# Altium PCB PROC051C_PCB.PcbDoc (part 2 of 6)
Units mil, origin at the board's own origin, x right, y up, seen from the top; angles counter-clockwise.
Board outline 3304.03 x 2647.77 mil, 6 copper layers (TOP, L2, L3, L4, L5, BOTTOM), stack 55.54 mil thick; 370 components, 273 nets, 1273 pads, 1381 vias.
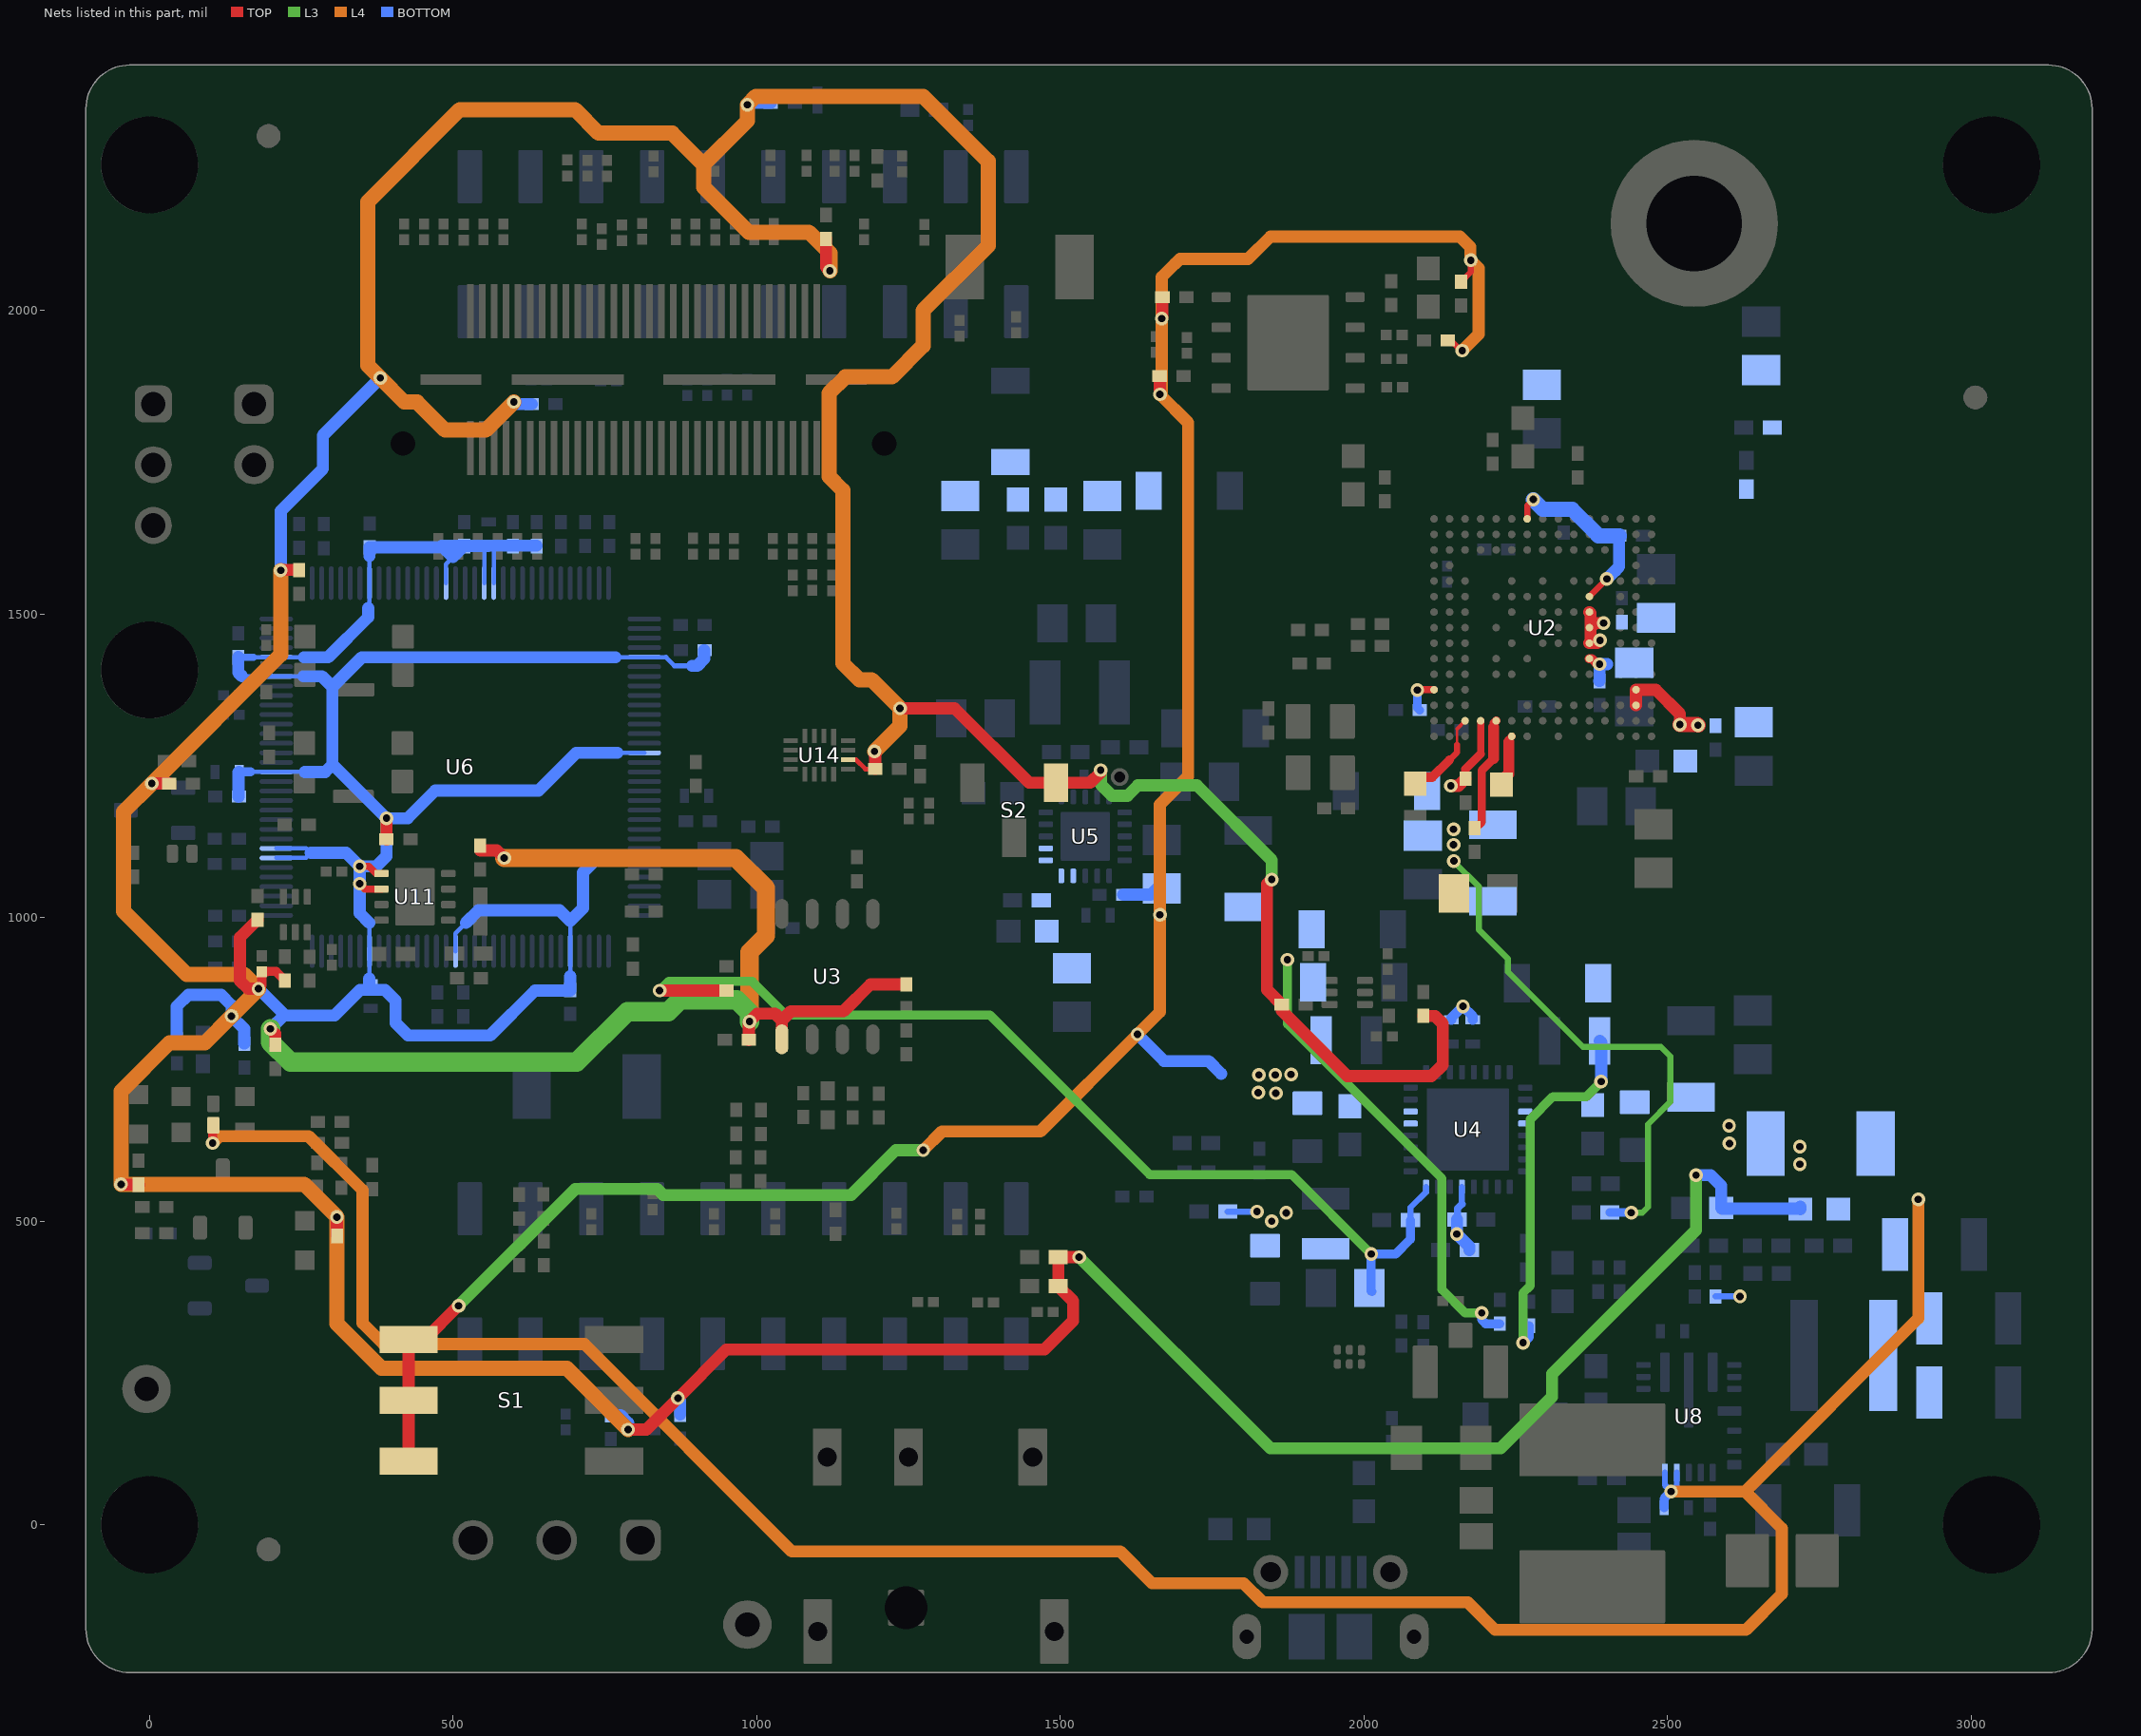
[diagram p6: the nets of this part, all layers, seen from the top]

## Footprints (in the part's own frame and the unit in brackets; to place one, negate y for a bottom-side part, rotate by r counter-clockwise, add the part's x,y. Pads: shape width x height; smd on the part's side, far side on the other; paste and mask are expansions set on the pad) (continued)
PDT0128A [mm] "Thin QFP, 128-Leads, Body 14x14mm, Pitch 0.4mm"
  oval 1.4x0.2 smd: 1(-7.7,6.2) 2(-7.7,5.8) 3(-7.7,5.4) 4(-7.7,5) 5(-7.7,4.6) 6(-7.7,4.2) 7(-7.7,3.8) 8(-7.7,3.4) 9(-7.7,3) 10(-7.7,2.6) 11(-7.7,2.2) 12(-7.7,1.8) 13(-7.7,1.4) 14(-7.7,1) 15(-7.7,0.6) 16(-7.7,0.2) 17(-7.7,-0.2) 18(-7.7,-0.6) 19(-7.7,-1) 20(-7.7,-1.4) 21(-7.7,-1.8) 22(-7.7,-2.2) 23(-7.7,-2.6) 24(-7.7,-3) 25(-7.7,-3.4) 26(-7.7,-3.8) 27(-7.7,-4.2) 28(-7.7,-4.6) 29(-7.7,-5) 30(-7.7,-5.4) 31(-7.7,-5.8) 32(-7.7,-6.2) 65(7.7,-6.2) 66(7.7,-5.8) 67(7.7,-5.4) 68(7.7,-5) 69(7.7,-4.6) 70(7.7,-4.2) 71(7.7,-3.8) 72(7.7,-3.4) 73(7.7,-3) 74(7.7,-2.6) 75(7.7,-2.2) 76(7.7,-1.8) 77(7.7,-1.4) 78(7.7,-1) 79(7.7,-0.6) 80(7.7,-0.2) 81(7.7,0.2) 82(7.7,0.6) 83(7.7,1) 84(7.7,1.4) 85(7.7,1.8) 86(7.7,2.2) 87(7.7,2.6) 88(7.7,3) 89(7.7,3.4) 90(7.7,3.8) 91(7.7,4.2) 92(7.7,4.6) 93(7.7,5) 94(7.7,5.4) 95(7.7,5.8) 96(7.7,6.2)
  oval 0.2x1.4 smd: 33(-6.2,-7.7) 34(-5.8,-7.7) 35(-5.4,-7.7) 36(-5,-7.7) 37(-4.6,-7.7) 38(-4.2,-7.7) 39(-3.8,-7.7) 40(-3.4,-7.7) 41(-3,-7.7) 42(-2.6,-7.7) 43(-2.2,-7.7) 44(-1.8,-7.7) 45(-1.4,-7.7) 46(-1,-7.7) 47(-0.6,-7.7) 48(-0.2,-7.7) 49(0.2,-7.7) 50(0.6,-7.7) 51(1,-7.7) 52(1.4,-7.7) 53(1.8,-7.7) 54(2.2,-7.7) 55(2.6,-7.7) 56(3,-7.7) 57(3.4,-7.7) 58(3.8,-7.7) 59(4.2,-7.7) 60(4.6,-7.7) 61(5,-7.7) 62(5.4,-7.7) 63(5.8,-7.7) 64(6.2,-7.7) 97(6.2,7.7) 98(5.8,7.7) 99(5.4,7.7) 100(5,7.7) 101(4.6,7.7) 102(4.2,7.7) 103(3.8,7.7) 104(3.4,7.7) 105(3,7.7) 106(2.6,7.7) 107(2.2,7.7) 108(1.8,7.7) 109(1.4,7.7) 110(1,7.7) 111(0.6,7.7) 112(0.2,7.7) 113(-0.2,7.7) 114(-0.6,7.7) 115(-1,7.7) 116(-1.4,7.7) 117(-1.8,7.7) 118(-2.2,7.7) 119(-2.6,7.7) 120(-3,7.7) 121(-3.4,7.7) 122(-3.8,7.7) 123(-4.2,7.7) 124(-4.6,7.7) 125(-5,7.7) 126(-5.4,7.7) 127(-5.8,7.7) 128(-6.2,7.7)
  silkscreen extent -7.7,-6.3 6.3,6.99, body extent -8,-8 8,8, height 1.07
RGR0020A [mm] "QFN, 20-Leads, Body 3.5x3.5mm, Pitch 0.5mm, Thermal Pad 2.05x2.05mm, TI Recommended"
  rrect42% 0.6x0.24 smd: 1(-1.65,1) 2(-1.65,0.5) 3(-1.65,0) 4(-1.65,-0.5) 5(-1.65,-1) 11(1.65,-1) 12(1.65,-0.5) 13(1.65,0) 14(1.65,0.5) 15(1.65,1)
  rrect42% 0.24x0.6 smd: 6(-1,-1.65) 7(-0.5,-1.65) 8(0,-1.65) 9(0.5,-1.65) 10(1,-1.65) 16(1,1.65) 17(0.5,1.65) 18(0,1.65) 19(-0.5,1.65) 20(-1,1.65)
  rrect5% 2.05x2.05 smd paste-1.025: 21(0,0)
  silkscreen extent -1.97,-1.97 1.97,1.97, body extent -1.75,-1.75 1.75,1.75, height 1
RHB0032N [mm] "QFN, 32-Leads, Body 5x5mm, Pitch 0.5mm, Thermal Pad 3.45x3.45mm"
  rrect40% 0.6x0.25 smd: 1(-2.4,1.75) 2(-2.4,1.25) 3(-2.4,0.75) 4(-2.4,0.25) 5(-2.4,-0.25) 6(-2.4,-0.75) 7(-2.4,-1.25) 8(-2.4,-1.75) 17(2.4,-1.75) 18(2.4,-1.25) 19(2.4,-0.75) 20(2.4,-0.25) 21(2.4,0.25) 22(2.4,0.75) 23(2.4,1.25) 24(2.4,1.75)
  rrect40% 0.25x0.6 smd: 9(-1.75,-2.4) 10(-1.25,-2.4) 11(-0.75,-2.4) 12(-0.25,-2.4) 13(0.25,-2.4) 14(0.75,-2.4) 15(1.25,-2.4) 16(1.75,-2.4) 25(1.75,2.4) 26(1.25,2.4) 27(0.75,2.4) 28(0.25,2.4) 29(-0.25,2.4) 30(-0.75,2.4) 31(-1.25,2.4) 32(-1.75,2.4)
  rrect3% 3.45x3.45 smd paste-1.725: 33(0,0)
  rrect7% 1.49x1.49 on Bottom Paste: ""(-0.845,-0.845) ""(-0.845,0.845) ""(0.845,-0.845) ""(0.845,0.845)
  silkscreen extent -2.72,-2.73 2.72,2.73, body extent -2.5,-2.5 2.5,2.5, height 0.9
RNL0022A_NV [mm] "VQFN-HR-22"
  rrect25% 0.6x0.4 smd: 1(-1.9,2) 17(1.9,2)
  rrect40% 0.6x0.25 smd: 2(-1.9,1.425) 3(-1.9,0.575) 5(-1.9,-1.175) 6(-1.9,-1.675) 7(-1.9,-2.175) 11(1.9,-2.175) 12(1.9,-1.675) 13(1.9,-1.175) 15(1.9,0.575) 16(1.9,1.425)
  rrect25% 1x0.4 smd paste-0.25: 4(-1.7,-0.25) 14(1.7,-0.25)
  rrect25% 0.4x0.4 on Bottom Paste: 4A(-2,-0.25) 4B(-1.4,-0.25) 14A(1.4,-0.25) 14B(2,-0.25)
  rrect25% 0.4x1.65 smd paste-0.25: 8(-1,-1.875) 10(1,-1.875)
  rrect25% 0.4x0.66 on Bottom Paste: 8A(-1,-1.445) 8B(-1,-2.305) 10A(1,-1.445) 10B(1,-2.305)
  rrect25% 0.4x3.15 smd paste-0.25: 9(0,-1.125)
  rrect25% 0.4x0.63 on Bottom Paste: 9A(0,0.12) 9B(0,-0.71) 9C(0,-1.54) 9D(0,-2.37)
  rrect40% 0.25x0.75 smd: 18(1,2.325) 19(0.5,2.325) 20(0,2.325) 21(-0.5,2.325) 22(-1,2.325)
  body extent -2,-2.5 2,2.5, height 0.9
RSV0016A [mm] "QFN, 16-Leads, Body 1.8x2.6mm, Pitch 0.4mm, TI Recommended"
  rect 0.7x0.2 smd: 1(-0.75,0.6)
  rect 0.6x0.2 smd: 2(-0.8,0.2) 3(-0.8,-0.2) 4(-0.8,-0.6) 9(0.8,-0.6) 10(0.8,-0.2) 11(0.8,0.2) 12(0.8,0.6)
  rect 0.2x0.6 smd: 5(-0.6,-1.2) 6(-0.2,-1.2) 7(0.2,-1.2) 8(0.6,-1.2) 13(0.6,1.2) 14(0.2,1.2) 15(-0.2,1.2) 16(-0.6,1.2)
  silkscreen extent -1.08,-1.33 1.08,1.45, body extent -0.92,-1.32 0.92,1.33, height 0.56
SAMTEC_QSH-030-01-X-D-A [mm] "Receptacle, 0.5 mm, 30x2, TH"
  rect 2.27x0.279 smd: 1(-2.865,7.25) 2(2.865,7.25) 3(-2.865,6.75) 4(2.865,6.75) 5(-2.865,6.25) 6(2.865,6.25) 7(-2.865,5.75) 8(2.865,5.75) 9(-2.865,5.25) 10(2.865,5.25) 11(-2.865,4.75) 12(2.865,4.75) 13(-2.865,4.25) 14(2.865,4.25) 15(-2.865,3.75) 16(2.865,3.75) 17(-2.865,3.25) 18(2.865,3.25) 19(-2.865,2.75) 20(2.865,2.75) 21(-2.865,2.25) 22(2.865,2.25) 23(-2.865,1.75) 24(2.865,1.75) 25(-2.865,1.25) 26(2.865,1.25) 27(-2.865,0.75) 28(2.865,0.75) 29(-2.865,0.25) 30(2.865,0.25) 31(-2.865,-0.25) 32(2.865,-0.25) 33(-2.865,-0.75) 34(2.865,-0.75) 35(-2.865,-1.25) 36(2.865,-1.25) 37(-2.865,-1.75) 38(2.865,-1.75) 39(-2.865,-2.25) 40(2.865,-2.25) 41(-2.865,-2.75) 42(2.865,-2.75) 43(-2.865,-3.25) 44(2.865,-3.25) 45(-2.865,-3.75) 46(2.865,-3.75) 47(-2.865,-4.25) 48(2.865,-4.25) 49(-2.865,-4.75) 50(2.865,-4.75) 51(-2.865,-5.25) 52(2.865,-5.25) 53(-2.865,-5.75) 54(2.865,-5.75) 55(-2.865,-6.25) 56(2.865,-6.25) 57(-2.865,-6.75) 58(2.865,-6.75) 59(-2.865,-7.25) 60(2.865,-7.25)
  round 0 hole 1.02 unplated mask+0.127: MH1(2.67,10.065) MH2(2.67,-10.065)
  rect 0.43x2.54 smd: MP1(0,8.065) MP4(0,-8.065)
  rect 0.43x4.7 smd: MP2(0,3.175) MP3(0,-3.175)
  silkscreen extent -3.9,-10.66 3.62,10.66, body extent -3.75,-10.64 3.75,10.67, height 3.25
SAMTEC_SSM-110-X-DV [mm] "Receptacle, 2.54mm, 10x2, SMT"
  rrect10% 1.02x2.22 smd: 1(-11.43,2.825) 2(-11.43,-2.825) 3(-8.89,2.825) 4(-8.89,-2.825) 5(-6.35,2.825) 6(-6.35,-2.825) 7(-3.81,2.825) 8(-3.81,-2.825) 9(-1.27,2.825) 10(-1.27,-2.825) 11(1.27,2.825) 12(1.27,-2.825) 13(3.81,2.825) 14(3.81,-2.825) 15(6.35,2.825) 16(6.35,-2.825) 17(8.89,2.825) 18(8.89,-2.825) 19(11.43,2.825) 20(11.43,-2.825)
  silkscreen extent -13.02,-2.54 12.7,2.54, body extent -12.7,-3.52 12.7,3.52, height 7.42
Samtec_TSW-103-07-T-S [mm] "Header, 2.54 mm, 3x1, TH"
  rrect50% 1.55x1.55 hole 1.02: 1(-2.54,0)
  round 1.55 hole 1.02: 2(0,0) 3(2.54,0)
  body extent -3.81,-1.27 3.81,1.27, height 8.39
SML-E1_Yellow [mm] "SMD, 2-Leads, Body 1.6x0.8mm"
  rect 0.8x0.8 smd: 1(0.825,0) 2(-0.825,0)
  silkscreen extent -1.8,-0.8 1.3,0.8, body extent -0.85,-0.45 0.85,0.45, height 0.46
SOD-882 [mm] "Skyworks"
  rrect42% 0.475x0.75 smd mask-3: 1(-0.412,0) 2(0.412,0)
  rrect42% 0.475x0.75 on Top Solder mask-3: 1(-0.412,0) 2(0.412,0)
  silkscreen extent -1.1,-0.35 -0.87,0.35, body extent -0.5,-0.3 0.5,0.3, height 0.5
SOT-23 [mm] "SOT23, 3-Leads, Body 2.9x1.3mm, Pitch 0.95mm, Lead Span 2.5mm, IPC Medium Density"
  rrect50% 1x0.6 smd: 1(-1.2,0.95) 2(-1.2,-0.95) 3(1.2,0)
  silkscreen extent -1.62,-1.5 0.7,1.5, body extent -1.16,-1.45 1.21,1.45, height 1
SW_219-3MST [mm] "SMD, 6-Leads, Body 6.7x9.09mm, Pitch 2.54mm"
  rect 2.44x1.13 smd: 1(-4.3,2.54) 2(-4.3,0) 3(-4.3,-2.54) 4(4.3,-2.54) 5(4.3,0) 6(4.3,2.54)
  silkscreen extent -3.35,-4.54 3.35,4.54, body extent -4.95,-4.55 4.96,4.55, height 4.3
SW_CJS_1201A [mm] "Copal- Electronics"
  rect 1x1.6 smd paste+0 mask+0.05: 1(-1.75,-1.15) 2(0,1.15) 3(1.75,-1.15)
  silkscreen extent -3,-1.6 -2.7,-0.8, body extent -3,-1.55 3,1.55, height 2.51
SW_KMR243GLFG [mm] "SMD, 5-Leads, Body 4.2x2.8mm"
  rrect11% 0.9x1 smd: 1(-2.05,0.8) 2(2.05,0.8) 3(-2.05,-0.8) 4(2.05,-0.8)
  rrect18% 1.7x0.55 smd: 5(0,1.425)
  silkscreen extent -3.1,0.7 -2.9,0.9, body extent -2.3,-1.4 2.3,1.4, height 1.92
TI_STACKED_OVERLAY_SMALL [mil]
  silkscreen extent -418,-98 418,98
TP_H045P075 [mm] "TP_H0.45P0.75"
  round 0.75 hole 0.45: 1(0,0)
TSW-102-07-G-S [mm] "Samtec 100mil, 1x2, 230 mil above insulator"
  rrect50% 1.65x1.65 hole 1.016: 1(-1.27,0)
  round 1.65 hole 1.016: 2(1.27,0)
  body extent -2.54,-1.27 2.54,1.27, height 8.38
WEEE_Minimum [mil] "WEEElie bin"
  silkscreen extent -95,-172 99,104
WSON-8L_6x5MM_EP [mm] "SMD, 8-Leads, Body 6x5mm, Pitch 1.27mm"
  rrect25% 0.8x0.4 smd: 1(-2.8,1.905) 2(-2.8,0.635) 3(-2.8,-0.635) 4(-2.8,-1.905) 5(2.8,-1.905) 6(2.8,-0.635) 7(2.8,0.635) 8(2.8,1.905)
  rrect3% 3.4x4 smd paste-3: 9(0,0)
  rrect7% 1.468x1.698 on Top Paste: ""(-0.834,-0.949) ""(-0.834,0.949) ""(0.834,-0.949) ""(0.834,0.949)
  silkscreen extent -3.2,-2.7 3.2,2.7, body extent -3.05,-2.55 3.05,2.55, height 0.8
XAL5030 [mil] "Coilcraft XAL5030 12/12/11"
  rect 46x183 smd: 1(-65,0) 2(65,0)
  silkscreen extent -108,-112 108,112, body extent -108,-112 108,112, height 122

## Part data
C1 C13 C14 C33 C36 C54 C94: library part CMP-0007136-5, "CAP, CERM, 1 uF, 16 V, +/- 10%, X7R, AEC-Q200 Grade 1, 0603", Cap_Case=0603, Manufacturer=MuRata, Supplier Part Number 1=490-5241-6-ND, TempCo=X7R, Tolerance_%=10%, Value1=Unknown, Value2=16V, ValueDisplayed=1uF
C2: library part CMP-0006325-2, "CAP, CERM, 0.1 uF, 50 V, +/- 10%, X7R, AEC-Q200 Grade 1, 0402", Cap_Case=0402, Manufacturer=TDK, Supplier Part Number 1=445-6899-1-ND, TempCo=X7R, Tolerance_%=10%, Value1="0.039064 ohm", Value2=50V, ValueDisplayed=0.1uF
C3 C5 C7 C10 C12 C39 C47 C48 C51 C53 C56 C57 C84 C90: library part CMP-0078265-1, "CAP, CERM, 0.22 µF, 16 V,+/- 10%, X7R, AEC-Q200 Grade 1, 0402", Cap_Case=0402, Manufacturer=MuRata, Supplier Part Number 1=490-10671-1-ND, TempCo=X7R, Tolerance_%=10%, Value2=16V, ValueDisplayed=0.22µF
C4 C6 C11 C22: library part CMP-0006351-2, "CAP, CERM, 0.1 uF, 16 V, +/- 10%, X7R, 0402", Cap_Case=0402, Manufacturer=MuRata, Supplier Part Number 1=490-4759-2-ND, TempCo=X7R, Tolerance_%=10%, Value1=Unknown, Value2=16V, ValueDisplayed=0.1uF
C8: library part CMP-0064969-1, "CAP, CERM, 0.1 uF, 10 V,+/- 10%, X7S, 0201", Cap_Case=0201, Manufacturer=MuRata, Supplier Part Number 1=490-14450-1-ND, TempCo=X7S, Tolerance_%=10%, Value1=Unknown, Value2=10V, ValueDisplayed=0.1uF
C9 C15: library part CMP-0006367-2, "CAP, CERM, 4.7 pF, 50 V, +/- 2%, C0G/NP0, 0402", Cap_Case=0402, Manufacturer=MuRata, Supplier Part Number 1=490-8102-1-ND, TempCo=C0G/NP0, Tolerance_%=2%, Value1=Unknown, Value2=50V, ValueDisplayed=4.7pF
C16 C20 C42 C43 C49 C64 C67 C71 C75 C91 C92 C97: library part CMP-0078241-1, "CAP, CERM, 0.1 µF, 10 V,+/- 10%, X7R, 0402", Cap_Case=0402, Manufacturer=Kemet, Supplier Part Number 1=399-3520-1-ND, TempCo=X7R, Tolerance_%=10%, Value2=10V, ValueDisplayed=0.1µF
C17 C40 C45 C52 C55 C58 C65 C80 C83 C95 C96 C98 C100 C102 C103 C104: library part CMP-0008017-2, "CAP, CERM, 10 uF, 10 V, +/- 10%, X7R, 0805", Cap_Case=0805, Manufacturer=MuRata, Supplier Part Number 1=490-10674-1-ND, TempCo=X7R, Tolerance_%=10%, Value1=Unknown, Value2=10V, ValueDisplayed=10uF
C18: library part CMP-0006717-2, "CAP, CERM, 0.47 uF, 6.3 V, +/- 10%, X7R, 0402", Cap_Case=0402, Manufacturer="Taiyo Yuden", PartNumber=JMK105B7474KVHF, Supplier Part Number 1=587-3765-1-ND, TempCo=X7R, Tolerance_%=10%, Value1=Unknown, Value2=6.3V, ValueDisplayed=0.47uF
C19 C37 C99 C105: library part CMP-0008770-2, "CAP, CERM, 22 uF, 6.3 V, +/- 10%, X7R, AEC-Q200 Grade 1, 1206", Cap_Case=1206_180, Manufacturer=TDK, Supplier Part Number 1=445-7884-1-ND, TempCo=X7R, Tolerance_%=10%, Value1="0.001872 ohm", Value2=6.3V, ValueDisplayed=22uF
C21 C25: library part CMP-0009155-2, "CAP, CERM, 10 uF, 25 V, +/- 20%, X7R, AEC-Q200 Grade 1, 1210", Cap_Case=1210, Manufacturer=TDK, Supplier Part Number 1=445-5720-1-ND, TempCo=X7R, Tolerance_%=20%, Value1=Unknown, Value2=25V, ValueDisplayed=10uF
C23 C27: library part CMP-0085252-1, "CAP, CERM, 0.047 µF, 50 V,+/- 5%, X7R, 0603", Cap_Case=0603, Manufacturer=AVX, TempCo=X7R, Tolerance_%=5%, Value2=50V, ValueDisplayed=0.047µF
C24: library part CMP-0006361-2, "CAP, CERM, 4700 pF, 50 V, +/- 10%, X7R, AEC-Q200 Grade 1, 0402", Cap_Case=0402, Manufacturer=MuRata, Supplier Part Number 1=490-4915-1-ND, TempCo=X7R, Tolerance_%=10%, Value1=Unknown, Value2=50V, ValueDisplayed=4700pF
C26: library part CMP-0078216-1, "CAP, TA, 47 µF, 10 V, +/- 10%, SMD", Cap_Case=3528-21, Manufacturer=Kemet, Supplier Part Number 1=399-9728-1-ND, Tolerance_%=10%, Value2=10V, ValueDisplayed=47µF
C28 C34 C77 C78: library part CMP-0006201-2, "CAP, CERM, 0.1 uF, 16 V, +/- 10%, X7R, 0402", Cap_Case=0402, Manufacturer=AVX, PartNumber=0402YC104KAT2A, Supplier Part Number 1=478-7888-1-ND, TempCo=X7R, Tolerance_%=10%, Value1=Unknown, Value2=16V, ValueDisplayed=0.1uF
C29 C30 C31: library part CMP-0009174-2, "CAP, CERM, 22 uF, 16 V, +/- 10%, X7R, 1210", Cap_Case=1210, Manufacturer=MuRata, Supplier Part Number 1=490-5242-1-ND, TempCo=X7R, Tolerance_%=10%, Value1=Unknown, Value2=16V, ValueDisplayed=22uF
C32 C79: library part CMP-0076706-1, "CAP, CERM, 4.7 µF, 25 V,+/- 10%, X7R, AEC-Q200 Grade 1, 0805", Cap_Case=2x1.25x1.25mm, Manufacturer=TDK, Supplier Part Number 1=445-6967-1-ND, TempCo=X7R, Tolerance_%=10%, Value2=25V, ValueDisplayed=4.7µF
C35 C46 C81: library part CMP-0007995-2, "CAP, CERM, 10 uF, 16 V, +/- 10%, X7R, 0805", Cap_Case=0805, Manufacturer="Samsung Electro-Mechanics", PartNumber=CL21B106KOQNNNE, TempCo=X7R, Tolerance_%=10%, Value1=Unknown, Value2=16V, ValueDisplayed=10uF
C38 C60 C68: library part CMP-0008809-2, "CAP, CERM, 22 uF, 6.3 V, +/- 10%, X7R, AEC-Q200 Grade 1, 1206", Cap_Case=1206, Manufacturer=MuRata, Supplier Part Number 1=490-4843-1-ND, TempCo=X7R, Tolerance_%=10%, Value1=Unknown, Value2=6.3V, ValueDisplayed=22uF
C41 C61 C62 C76: library part CMP-0006349-2, "CAP, CERM, 1 uF, 10 V, +/- 10%, X7S, AEC-Q200 Grade 1, 0402", Cap_Case=0402, Manufacturer=MuRata, Supplier Part Number 1=81-GCM155C71A105KE8D, TempCo=X7S, Tolerance_%=10%, Value1=Unknown, Value2=10V, ValueDisplayed=1uF
C44: library part CMP-0009172-2, "CAP, CERM, 47 uF, 6.3 V, +/- 10%, X7R, AEC-Q200 Grade 1, 1210", Cap_Case=1210, Manufacturer=MuRata, Supplier Part Number 1=490-4844-1-ND, TempCo=X7R, Tolerance_%=10%, Value1=Unknown, Value2=6.3V, ValueDisplayed=47uF
C50 C66 C69: library part CMP-0078218-1, "CAP, CERM, 0.01 µF, 16 V,+/- 10%, X7R, 0402", Cap_Case=0402, Manufacturer=Kemet, Supplier Part Number 1=399-1038-1-ND, TempCo=X7R, Tolerance_%=10%, Value2=16V, ValueDisplayed=0.01µF
C59: library part CMP-0008017-2, "CAP, CERM, 10 uF, 10 V, +/- 10%, X7R, 0805", Cap_Case=0805, Manufacturer=MuRata, PartNumber=GCM21BR71A106KE22L, Supplier Part Number 1=490-10674-1-ND, TempCo=X7R, Tolerance_%=10%, Value1=Unknown, Value2=10V, ValueDisplayed=10uF
C63 C70: library part CMP-0087060-3, "Cap Ceramic 8pF 50V C0G 0.5pF SMD 0402 125C Paper T/R", Manufacturer="Murata Electronics North America", TempCo=30ppm/°C
C72 C73 C101: library part CMP-0006352-2, "CAP, CERM, 0.01 uF, 25 V, +/- 10%, X7R, 0402", Cap_Case=0402, Manufacturer=MuRata, Supplier Part Number 1=490-6043-2-ND, TempCo=X7R, Tolerance_%=10%, Value1=Unknown, Value2=25V, ValueDisplayed=0.01uF
C74 C86: library part CMP-0006302-2, "CAP, CERM, 2.2 uF, 10 V, +/- 10%, X7S, 0402", Cap_Case=0402_065, Manufacturer=TDK, Supplier Part Number 1=445-9097-1-ND, TempCo=X7S, Tolerance_%=10%, Value1="0.005925 ohm", Value2=10V, ValueDisplayed=2.2uF
C82: library part CMP-0006201-2, "CAP, CERM, 0.1 uF, 16 V, +/- 10%, X7R, 0402", Cap_Case=0402, Manufacturer=AVX, Supplier Part Number 1=478-7888-1-ND, TempCo=X7R, Tolerance_%=10%, Value1=Unknown, Value2=16V, ValueDisplayed=0.1uF
C85: library part CMP-0006624-2, "CAP, CERM, 1 uF, 6.3 V, +/- 20%, X7R, 0402", Cap_Case=0402, Manufacturer=MuRata, Supplier Part Number 1=490-9665-1-ND, TempCo=X7R, Tolerance_%=20%, Value1=Unknown, Value2=6.3V, ValueDisplayed=1uF
C87 C89: library part CMP-0007134-5, "CAP, CERM, 2.2 uF, 6.3 V, +/- 10%, X7R, AEC-Q200 Grade 1, 0603", Cap_Case=0603, Manufacturer=MuRata, Supplier Part Number 1=490-5316-1-ND, TempCo=X7R, Tolerance_%=10%, Value1=Unknown, Value2=6.3V, ValueDisplayed=2.2uF
C88: library part CMP-0006242-2, "CAP, CERM, 33 pF, 50 V, +/- 5%, C0G/NP0, 0402", Cap_Case=0402, Manufacturer=Kemet, Supplier Part Number 1=399-1017-1-ND, TempCo=C0G/NP0, Tolerance_%=5%, Value1=Unknown, Value2=50V, ValueDisplayed=33pF
C93: library part CMP-0084680-1, "CAP, CERM, 22 µF, 25 V,+/- 20%, X5R, AEC-Q200 Grade 3, 0805", Cap_Case=0805, Manufacturer=MuRata, TempCo=X5R, Tolerance_%=20%, Value2=25V, ValueDisplayed=22µF
"CAUTION HOT SURFACE": library part CMP-0074837-1, "IEC 61010-1 Hot Surface Warning"
D2: library part CMP-0078187-2, "Diode, Schottky,  V, 0.01 A, SOD-882", Manufacturer="Skyworks Solutions", Value1=0.01A, Value2=0.34V
D5: library part CMP-0067682-2, "LED, Green, SMD", Color=Green, Manufacturer=Kingbright, Power_TotalModule=75mW, Value1=0.075W, Value2=2.1V
DS1 DS2: library part CMP-0002902-2, "LED, Red, SMD", Color=Red, Manufacturer=OSRAM, Value1=W, Value2=1.8V
DS3 DS4: library part CMP-0002977-3, "LED, Yellow, SMD", Color=yellow, Manufacturer=Rohm, Power_TotalModule=54mW, Value1=0.054W, Value2=2.2V
"ESD Susceptible": library part CMP-0074840-1, "ESD Susceptible Symbol"
F1: library part CMP-0003458-2, "Fuse, 5 A, 32VAC/VDC, SMD", Irating_A=5A, Manufacturer=Littelfuse, Supplier Part Number 1=F1608CT-ND
FID1 FID2 FID3 FID4 FID5 FID6: library part CMP-0077181-1, "Fiducial mark.  There is nothing to buy or mount.", Manufacturer=N/A
J1: library part CMP-0075524-1, "Receptacle, 0.5 mm, 30x2, Gold, TH", Color=Black, Manufacturer=Samtec, Supplier Part Number 1=SAM8180-ND
J2: library part CMP-0055788-1, "UMC Straight Jack Receptacle, 50 Ohm, Gold, SMT", Manufacturer="Cinch Connectivity", Supplier Part Number 1=J983CT-ND
J3: library part CMP-0075352-1, "Terminal Block, 3.5mm, 3x1, Tin, R/A, TH", Color=Blue, Current_A=10A, Manufacturer="On-Shore Technology", Supplier Part Number 1=ED2636-ND, Voltage_V=125V
J5 J6: library part CMP-0078182-1, "Receptacle, 2.54mm, 10x2, Gold with Tin tail, SMT", Color=Black, Current_A=5.2A, Manufacturer=Samtec, Supplier Part Number 1=SAM1150-10-ND, Voltage_V=405V
J8: library part CMP-0055293-1, "Connector, Receptacle, Micro-USB Type B, R/A, Bottom Mount SMT", Manufacturer=Molex, Supplier Part Number 1=WM1399CT-ND
L1: library part CMP-0061001-2, "Inductor, Shielded, Composite, 2.2 µH, 9.2 A, 0.01 ohm, AEC-Q200 Grade 1, SMD", Manufacturer=Coilcraft, Value1="0.01 ohm", Value2=9.2A, ValueDisplayed=2.2uH
L2 L3: library part CMP-0058944-1, "Inductor, Shielded, 470 nH, 4.7 A, 0.021 ohm, SMD", Manufacturer="MuRata Toko", Value1="0.021 ohm", Value2=4.7A, ValueDisplayed=470nH
L4: library part CMP-0058938-1, "Inductor, Shielded, 1 uH, 3.8 A, 0.035 ohm, AEC-Q200 Grade 1, SMD", Manufacturer="MuRata Toko", Value1="0.035 ohm", Value2=3.8A, ValueDisplayed=1uH
L5 L6 L10: library part CMP-0083745-1, "Inductor, Wirewound, Ferrite, 100 nH, 2.85 A, 0.024 ohm, AEC-Q200 Grade 1, SMD", Manufacturer=TDK, Value1="0.024 ohm", Value2=2.85A, ValueDisplayed=100nH
L7: library part CMP-0003388-1, "Ferrite Bead, 600 ohm @ 100 MHz, 4 A, 2220", Manufacturer="Laird-Signal Integrity Products", Supplier Part Number 1=240-2427-1-ND, Value1="0.025 ohm", Value2=4A, ValueDisplayed="600 ohm"
L8 L9: library part CMP-0077879-2, "Ferrite Bead, 120 ohm @ 100 MHz, 1.9 A, 0603", Manufacturer=MuRata, Supplier Part Number 1=490-13261-1-ND, Value1="0.04 ohm", Value2=1.9A, ValueDisplayed="120 ohm"
LBL1: library part CMP-0003625-1, "Thermal Transfer Printable Labels, 0.650\" W x 0.200\" H - 10,000 per roll", Manufacturer=Brady, PartNumber=THT-14-423-10, Supplier Part Number 1=97C5133
Logo1: library part CMP-0074838-1, "Texas Instrument Corporate Signature"
Logo2: library part CMP-0074847-1, "FCC_disclaimer"
LOGO3: library part CMP-0074844-1
Logo4: library part CMP-0074769-1
P1: library part CMP-0075530-2, "Header, 2.54 mm, 3x1, Tin, TH", Color=Black, Current_A=6.3A, Manufacturer=Samtec, Supplier Part Number 1=SAM1035-03-ND, Voltage_V=550V
P6: library part CMP-0081851-1, "DC Power Jack, R/A, TH", Color=Black, Current_A=5A, Manufacturer="CUI Inc.", Supplier Part Number 1=CP-051AH-ND, Voltage_V=24V
P7: library part CMP-0075405-2, "Header, 100mil, 2x1, Gold, TH", Color=Black, Current_A=6.3A, Manufacturer=Samtec, Supplier Part Number 1=SAM1029-02-ND, Voltage_V=550V
Q1 Q2: library part CMP-0000947-2, "MOSFET, N-CH, 100 V, 0.17 A, SOT-23", Alternate Manufacturer=None, Manufacturer="Fairchild Semiconductor", Supplier Part Number 1=BSS123NCT-ND, Value1=1, Value2="1.8 nC"
R1 R2 R4 R5 R6 R7 R8 R9 R10 R17 R18 R19 R20 R21 R22 R23 R24 R25 R26 R27 R28 R29 R30 R31 R32 R33 R35 R36 R48 R49 R50 R51 R52 R53 R58 R59 R60 R62 R63 R64 R65 R66 R67 R69 R70 R71 R72 R75 R76 R94 R102 R104 R105 R106 R108 R109 R111 R135 R136 R162 R163 R164 R165 R166 R167 R168 R169 R198 R199 R201: library part CMP-0027008-4, "RES, 0, 5%, 0.05 W, 0201", Manufacturer=Vishay-Dale, Power_W=50mW, Supplier Part Number 1=72M6743, TempCo=ppm/C, Tolerance_%=5%, Value2=0.05W, Value_Code=0000, ValueDisplayed=0
R3 R13 R14 R15 R16 R41 R43 R73 R74 R86 R89 R91 R98 R113 R155 R158 R177 R194 R197 R208: library part CMP-0025958-3, "RES, 10.0 k, 1%, 0.063 W, AEC-Q200 Grade 0, 0402", Manufacturer=Vishay-Dale, Power_W=63mW, Supplier Part Number 1=541-10.0KLCT-ND, TempCo="100 ppm/C", Tolerance_%=1%, Value2=0.063W, Value_Code=10k0, ValueDisplayed=10.0k
R11 R12 R37 R78 R97 R107 R128 R129 R141 R152 R178 R196 R200: library part CMP-0026992-3, "RES, 0, 5%, 0.1 W, AEC-Q200 Grade 0, 0402", Manufacturer=Panasonic, Power_W=100mW, Supplier Part Number 1=P0.0JCT-ND, TempCo="600 ppm/C", Tolerance_%=5%, Value2=0.1W, Value_Code=0000, ValueDisplayed=0
R34 R115 R156: library part CMP-0016044-3, "RES, 0, 5%, 0.75 W, AEC-Q200 Grade 0, 2010", Manufacturer=Vishay-Dale, Power_W=750mW, Supplier Part Number 1=541-0.0WCT-ND, TempCo=ppm/C, Tolerance_%=5%, Value2=0.75W, Value_Code=0000, ValueDisplayed=0
R38: library part CMP-0026395-2, "RES, 47.5 k, 1%, 0.063 W, AEC-Q200 Grade 0, 0402", Manufacturer=Vishay-Dale, Power_W=63mW, Supplier Part Number 1=541-47.5KLCT-ND, TempCo="100 ppm/C", Tolerance_%=1%, Value2=0.063W, Value_Code=47k5, ValueDisplayed=47.5k
R39 R40 R42 R44 R45: library part CMP-0027275-3, "RES, 33.2, 1%, 0.05 W, 0201", Manufacturer=Vishay-Dale, Power_W=50mW, Supplier Part Number 1=541-33.2ABCT-ND, TempCo="200 ppm/C", Tolerance_%=1%, Value2=0.05W, Value_Code=33R2, ValueDisplayed=33.2
R46 R100 R147 R157: library part CMP-0026822-3, "RES, 0, 5%, 0.063 W, AEC-Q200 Grade 0, 0402", Manufacturer=Vishay-Dale, Power_W=63mW, Supplier Part Number 1=541-0.0JCT-ND, TempCo="200 ppm/C", Tolerance_%=5%, Value2=0.063W, Value_Code=0000, ValueDisplayed=0
R47 R81 R119 R120 R121 R143 R144 R148 R149 R159 R188 R189: library part CMP-0026822-3, "RES, 0, 5%, 0.063 W, AEC-Q200 Grade 0, 0402", Manufacturer=Vishay-Dale, PartNumber=CRCW04020000Z0ED, Power_W=63mW, Supplier Part Number 1=541-0.0JCT-ND, TempCo="200 ppm/C", Tolerance_%=5%, Value2=0.063W, Value_Code=0000, ValueDisplayed=0
R54 R55 R56 R57 R179 R180 R181 R182 R183 R184: library part CMP-0078192-2, "RES, 20.0, 1%, 0.05 W, 0201", Manufacturer=Vishay-Dale, Power_W=50mW, Supplier Part Number 1=541-2947-1-ND, TempCo="200 ppm/C", Tolerance_%=1%, Value2=0.05W, Value_Code=20R0, ValueDisplayed=20.0
R61: library part CMP-0026658-1, "RES, 10.0 k, 1%, 0.1 W, 0402", Manufacturer=Panasonic, Power_W=100mW, Supplier Part Number 1=P10.0KLCT-ND, TempCo="100 ppm/C", Tolerance_%=1%, Value2=0.1W, Value_Code=10k0, ValueDisplayed=10.0k
R68 R77 R79 R80 R154: library part CMP-0026993-2, "RES, 100, 5%, 0.1 W, AEC-Q200 Grade 0, 0402", Manufacturer=Panasonic, Power_W=100mW, Supplier Part Number 1=P100JCT-ND, TempCo="200 ppm/C", Tolerance_%=5%, Value2=0.1W, Value_Code=100R, ValueDisplayed=100
R82: library part CMP-0026825-5, "RES, 10 k, 5%, 0.063 W, AEC-Q200 Grade 0, 0402", Manufacturer=Vishay-Dale, PartNumber=CRCW040210K0JNED, Power_W=63mW, Supplier Part Number 1=541-10KJCT-ND, TempCo="200 ppm/C", Tolerance_%=5%, Value2=0.063W, Value_Code=10k0, ValueDisplayed=10k
R83: library part CMP-0025754-4, "RES, 20, 5%, 0.1 W, AEC-Q200 Grade 0, 0603", Manufacturer=Vishay-Dale, Power_W=100mW, Supplier Part Number 1=541-20GCT-ND, TempCo="200 ppm/C", Tolerance_%=5%, Value2=0.1W, Value_Code=20R0, ValueDisplayed=20
R84: library part CMP-0026823-3, "RES, 100 k, 5%, 0.063 W, AEC-Q200 Grade 0, 0402", Manufacturer=Vishay-Dale, Power_W=63mW, Supplier Part Number 1=541-100KJCT-ND, TempCo="200 ppm/C", Tolerance_%=5%, Value2=0.063W, Value_Code=100k
R85 R87: library part CMP-0026491-2, "RES, 61.9, 1%, 0.063 W, AEC-Q200 Grade 0, 0402", Manufacturer=Vishay-Dale, Power_W=63mW, Supplier Part Number 1=541-61.9LCT-ND, TempCo="100 ppm/C", Tolerance_%=1%, Value2=0.063W, Value_Code=61R9, ValueDisplayed=61.9
R88 R96 R114: library part CMP-0026574-2, "RES, 82.5 k, 1%, 0.063 W, AEC-Q200 Grade 0, 0402", Manufacturer=Vishay-Dale, Power_W=63mW, Supplier Part Number 1=541-82.5KLCT-ND, TempCo="100 ppm/C", Tolerance_%=1%, Value2=0.063W, Value_Code=82k5, ValueDisplayed=82.5k
R90 R103 R117 R202: library part CMP-0078194-1, "RES, 360, 5%, 0.1 W, AEC-Q200 Grade 0, 0402", Manufacturer=Panasonic, Power_W=100mW, Supplier Part Number 1=P360JCT-ND, TempCo="200 ppm/C", Tolerance_%=5%, Value2=0.1W, Value_Code=360R, ValueDisplayed=360
R92 R95 R99: library part CMP-0026557-2, "RES, 7.87 k, 1%, 0.063 W, AEC-Q200 Grade 0, 0402", Manufacturer=Vishay-Dale, Power_W=63mW, Supplier Part Number 1=541-7.87KLCT-ND, TempCo="100 ppm/C", Tolerance_%=1%, Value2=0.063W, Value_Code=7k87, ValueDisplayed=7.87k
R93 R101 R112: library part CMP-0026542-2, "RES, 750, 1%, 0.063 W, AEC-Q200 Grade 0, 0402", Manufacturer=Vishay-Dale, Power_W=63mW, Supplier Part Number 1=541-750LCT-ND, TempCo="100 ppm/C", Tolerance_%=1%, Value2=0.063W, Value_Code=750R, ValueDisplayed=750
R110 R138 R172 R173: library part CMP-0025950-3, "RES, 100 k, 1%, 0.063 W, AEC-Q200 Grade 0, 0402", Manufacturer=Vishay-Dale, Power_W=63mW, Supplier Part Number 1=541-100KLCT-ND, TempCo="100 ppm/C", Tolerance_%=1%, Value2=0.063W, Value_Code=100k
R116 R160: library part CMP-0078212-1, "RES, 510, 5%, 0.1 W, AEC-Q200 Grade 0, 0402", Manufacturer=Panasonic, Power_W=100mW, Supplier Part Number 1=P510JCT-ND, TempCo="200 ppm/C", Tolerance_%=5%, Value2=0.1W, Value_Code=510R, ValueDisplayed=510
R118: library part CMP-0026878-3, "RES, 220, 5%, 0.063 W, AEC-Q200 Grade 0, 0402", Manufacturer=Vishay-Dale, Power_W=63mW, Supplier Part Number 1=541-220JCT-ND, TempCo="200 ppm/C", Tolerance_%=5%, Value2=0.063W, Value_Code=220R, ValueDisplayed=220
R122: library part CMP-0083631-1, "RES, 12.1 k, 0.1%, 0.063 W, AEC-Q200 Grade 0, 0402", Manufacturer=Panasonic, Power_W=63mW, Supplier Part Number 1=P12.1KDCCT-ND, TempCo="25 ppm/C", Tolerance_%=0.1%, Value2=0.063W, Value_Code=12k1, ValueDisplayed=12.1k
R123 R124 R126 R127 R140: library part CMP-0026071-3, "RES, 1.00 k, 1%, 0.063 W, AEC-Q200 Grade 0, 0402", Manufacturer=Vishay-Dale, Power_W=63mW, Supplier Part Number 1=541-1.00KLCT-ND, TempCo="100 ppm/C", Tolerance_%=1%, Value2=0.063W, Value_Code=1k00, ValueDisplayed=1.00k
R125: library part CMP-0026413-2, "RES, 4.87 k, 1%, 0.063 W, AEC-Q200 Grade 0, 0402", Manufacturer=Vishay-Dale, Power_W=63mW, Supplier Part Number 1=541-4.87KLCT-ND, TempCo="100 ppm/C", Tolerance_%=1%, Value2=0.063W, Value_Code=4k87, ValueDisplayed=4.87k
R130 R133 R137 R161 R175: library part CMP-0025884-3, "RES, 0, 5%, 0.125 W, 0603", Manufacturer=Vishay/Beyschlag, Power_W=125mW, Supplier Part Number 1=MCT0603-0.0-ZZCT-ND, TempCo=ppm/C, Tolerance_%=5%, Value2=0.125W, Value_Code=0000, ValueDisplayed=0
R131 R132: library part CMP-0026918-5, "RES, 3.3 k, 5%, 0.063 W, AEC-Q200 Grade 0, 0402", Manufacturer=Vishay-Dale, PartNumber=CRCW04023K30JNED, Power_W=63mW, Supplier Part Number 1=541-3.3KJCT-ND, TempCo="200 ppm/C", Tolerance_%=5%, Value2=0.063W, Value_Code=3k30, ValueDisplayed=3.3k
R134: library part CMP-0026404-2, "RES, 49.9, 1%, 0.063 W, AEC-Q200 Grade 0, 0402", Manufacturer=Vishay-Dale, Power_W=63mW, Supplier Part Number 1=541-49.9LCT-ND, TempCo="100 ppm/C", Tolerance_%=1%, Value2=0.063W, Value_Code=49R9, ValueDisplayed=49.9
R139: library part CMP-0026781-1, "RES, 4.87 k, 0.1%, 0.062 W, AEC-Q200 Grade 0, 0402", Manufacturer=Panasonic, Power_W=62mW, Supplier Part Number 1=P4.87KDCCT-ND, TempCo="25 ppm/C", Tolerance_%=0.1%, Value2=0.062W, Value_Code=4k87, ValueDisplayed=4.87k
R142 R186 R190: library part CMP-0026825-5, "RES, 10 k, 5%, 0.063 W, AEC-Q200 Grade 0, 0402", Manufacturer=Vishay-Dale, Power_W=63mW, Supplier Part Number 1=541-10KJCT-ND, TempCo="200 ppm/C", Tolerance_%=5%, Value2=0.063W, Value_Code=10k0, ValueDisplayed=10k
R145: library part CMP-0083632-1, "RES, 48.7 k, 0.1%, 0.063 W, AEC-Q200 Grade 0, 0402", Manufacturer=Panasonic, Power_W=63mW, Supplier Part Number 1=P48.7KDCCT-ND, TempCo="25 ppm/C", Tolerance_%=0.1%, Value2=0.063W, Value_Code=48k7, ValueDisplayed=48.7k
R146: library part CMP-0083657-1, "RES, 4.42 k, 0.1%, 0.063 W, AEC-Q200 Grade 0, 0402", Manufacturer=Panasonic, Power_W=63mW, Supplier Part Number 1=P18066CT-ND, TempCo="10 ppm/C", Tolerance_%=0.1%, Value2=0.063W, Value_Code=4k42, ValueDisplayed=4.42k
R150: library part CMP-0025951-3, "RES, 100, 1%, 0.063 W, AEC-Q200 Grade 0, 0402", Manufacturer=Vishay-Dale, Power_W=63mW, Supplier Part Number 1=541-100LCT-ND, TempCo="100 ppm/C", Tolerance_%=1%, Value2=0.063W, Value_Code=100R, ValueDisplayed=100
R151 R153: library part CMP-0078210-2, "RES, 330 k, 1%, 0.063 W, AEC-Q200 Grade 0, 0402", Manufacturer=Vishay-Dale, Power_W=63mW, Supplier Part Number 1=541-330KLCT-ND, TempCo="100 ppm/C", Tolerance_%=1%, Value2=0.063W, Value_Code=330k
R170 R171: library part CMP-0026244-2, "RES, 2.94 k, 1%, 0.063 W, AEC-Q200 Grade 0, 0402", Manufacturer=Vishay-Dale, Power_W=63mW, Supplier Part Number 1=541-2.94KLCT-ND, TempCo="100 ppm/C", Tolerance_%=1%, Value2=0.063W, Value_Code=2k94, ValueDisplayed=2.94k
R174: library part CMP-0078244-2, "RES, 30.0 k, 1%, 0.063 W, AEC-Q200 Grade 0, 0402", Manufacturer=Vishay-Dale, Power_W=63mW, Supplier Part Number 1=541-30.0KLCT-ND, TempCo="100 ppm/C", Tolerance_%=1%, Value2=0.063W, Value_Code=30k0, ValueDisplayed=30.0k
R193: library part CMP-0026207-2, "RES, 26.1 k, 1%, 0.063 W, AEC-Q200 Grade 0, 0402", Manufacturer=Vishay-Dale, Power_W=63mW, Supplier Part Number 1=541-26.1KLCT-ND, TempCo="100 ppm/C", Tolerance_%=1%, Value2=0.063W, Value_Code=26k1, ValueDisplayed=26.1k
S1: library part CMP-0002269-1, "Switch, SPST, Slide, Off-On, 3 Pos, 0.1A, 20V, SMD", CurrentRating_mA=100A, Manufacturer="CTS Electrocomponents", Supplier Part Number 1=CT2193MST-ND
S2: library part CMP-0002159-2, "Slide SW, SPDT 0.1A 50VDC", CurrentRating_mA=100A, Manufacturer="Copal Electronics", Supplier Part Number 1=563-1023-1-ND
SW1 SW2: library part CMP-0002325-1, "Switch, SPST-NO, Off-Mom, 0.01 A, 32 VDC, SMD", CurrentRating_mA=10A, Manufacturer="C&K Components", Supplier Part Number 1=401-1432-2-ND
TP1 TP3: library part CMP-0055138-1, "Test Point, Miniature, Black, TH", Color=Black, Manufacturer=Keystone, Supplier Part Number 1=36-5001-ND
TP2: library part CMP-0003719-1, "Testpoint", Manufacturer="Texas Instruments"
U1: library part CMP-0079267-1, "2.3V-3.6V, 16M-BIT [x 1/x 2/x 4] CMOS FLASH Memory, WSON-8", Manufacturer="Macronix International Co., LTD", Supplier Part Number 1=1092-1211-ND
U2: library part CMP-0078239-1, "AWR1843ABL, ABL0161B (FCBGA-161)", Alternate Manufacturer="Texas Instruments"
U3: library part CMP-0075992-1, "Automotive Fault Protected CAN Transceiver With Flexible Data-Rate, D0008A (SOIC-8)", Alternate Manufacturer="Texas Instruments", Alternate PartNumber=TCAN1042HGVDRQ1
U4: library part CMP-0078631-1, "Boost and Dual Buck Regulators With Diagnostic Functions, RHB0032N (VQFN-32)", Alternate Manufacturer="Texas Instruments"
U5: library part CMP-0077268-2, "Automotive 3A High-Accuracy Low-Noise Low-Dropout (LDO) Voltage Regulator, RGR0020A (VQFN-20)", Manufacturer="Texas Instruments"
U6: library part CMP-0029856-2, "Tiva C Series Microcontroller, 1024 KB Flash, 256 KB SRAM, 12 Bit, 20 Channels, -40 to 105 degC, 128-Pin TQFP (PDT), Green (RoHS & no Sb/Br), Tray", Manufacturer="Texas Instruments", Temperature Range="-40 to 105 degC"
U7: library part CMP-0033001-1, "Precision Micropower Shunt Voltage Reference, 0.5% accuracy, 2.5 V, 15 ppm / degC, 15 mA, -40 to 125 degC, 3-pin SOT-23 (DBZ), Green (RoHS & no Sb/Br)", Manufacturer="Texas Instruments", Rating=Catalog, Temp Coeff(Max)(ppm/ degree C)=100, Temp Coeff(Typ)(ppm/ degree C)=15
U8: library part CMP-0076346-4, "2.5A, 36 V Synchronous, 2.1MHz, Automotive Step Down DC-DC Converter, RNL0022A (VQFN-HR-22)", Alternate Manufacturer="Texas Instruments", Alternate PartNumber=LM536253QRNLTQ1, Operating Temprature Range="-40 to 150 C", PartNumber=LM536253QRNLRQ1, Rating=Automotive
U10: library part CMP-0043115-3, "4-Channel ESD Protection Array for High-Speed Data Interfaces, DRY0006A (USON-6)", Breakdown Voltage(Min)(V)=6, IO Capacitance(Typ)(pF)=1.6, IO Leakage Current(nA)=1, Manufacturer="Texas Instruments", Operating Temperature Range="-40 to 85 C", Rating=Catalog
U11: library part CMP-0036402-3, "Single Output High PSRR LDO, 1 A, Adjustable 1.2 to 5.5 V Output, 2.7 to 5.5 V Input, 8-pin SON (DRB), -40 to 125 degC, Green (RoHS & no Sb/Br)", Manufacturer="Texas Instruments"
U12 U13: library part CMP-0067397-2, "1.4V-Capable +/-0.5degC Temperature Sensor with Alert Function and I2C/SMBus interface in SOT-563, DRL0006A (SOT-OTHER-6)", Alternate Manufacturer="Texas Instruments", Alternate PartNumber=TMP112AIDRLT
U14: library part CMP-0067415-1, "10-Ohm Quad SPDT Analog Switch, RSV0016A (UQFN-16)", Alternate Manufacturer="Texas Instruments"
Y1: library part CMP-0004694-3, "Crystal, 40 MHz, 8pF, SMD", Frequency_Fixed=40MHz, Frequency Stability=+/-200ppm, Manufacturer=Kyocera, Supplier Part Number 1=581-CX3225SA40D0PTWC
Y2: library part CMP-0078214-2, "Crystal, 16 MHz, 15 ppm, 8 pF, AEC-Q200 Grade 1, SMD", Frequency_Fixed=16MHz, Frequency Stability="150 ppm", Frequency Tolerance="10 ppm", Load Capacitance="7.36 pF", Manufacturer=NDK, Supplier Part Number 1=644-1129-1-ND
ZZ1: library part CMP-0003616-3
ZZ2: library part CMP-0077236-1
ZZ3: library part CMP-0077237-1
ZZ4: library part CMP-0077238-1
ZZ5: library part AssemblyNote, Alternate Manufacturer=-

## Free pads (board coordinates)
  round 275.59 hole 157.48: 1(2543.95,2143.55)
  round 160 hole 160 unplated mask+5: ""(0,0) ""(0,1408.1) ""(0,2240) ""(3033.56,0) ""(3033.56,2240)

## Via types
v1: diameter 22.4, hole 12.2, TOP to BOTTOM, tented both sides, 810 vias
v2: diameter 13.77/15.74 (per signal layer), hole 5.9, TOP to L2, tented both sides, 528 vias
v3: diameter 19.68, hole 7.87, TOP to BOTTOM, 23 vias
v4: diameter 19.68, hole 7.87, TOP to BOTTOM, tented both sides, 7 vias
v5: diameter 22.4, hole 12.1, TOP to BOTTOM, tented both sides, 7 vias
v6: diameter 16, hole 8, TOP to BOTTOM, tented both sides, 4 vias
v7: diameter 13.77/15.74 (per signal layer), hole 5.9, TOP to L2, tented top, 1 vias
v8: diameter 22.4/22.4/22.4/22.4/22.4/22.4 (per signal layer), hole 12.2, TOP to BOTTOM, tented both sides, 1 vias

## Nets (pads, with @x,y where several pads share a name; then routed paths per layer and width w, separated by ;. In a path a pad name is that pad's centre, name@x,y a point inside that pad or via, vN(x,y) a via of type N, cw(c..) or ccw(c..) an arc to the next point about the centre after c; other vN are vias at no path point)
1V8: C38.1 L2.2 L6.1 R119.1 | length 616.2
  L3 w15: v1(2262,300) 2262,382 2274,394 2274,668 2311.29,705.29 2366.31,705.29 2390.62,729.6 v1(2390.62,730.13)
  BOTTOM w15: v1(2262,300) 2263,300 2272,309 R119.1@2272,328
  BOTTOM w20: L2.2@2388.34,797 2390.62,794.72 v1(2390.62,730.13)
1V24: C33.2 C34.1 C40.1 C60.1 C68.1 L3.2 L5.1 R121.1 U5.14 U5.15 U5.16 U5.17 | length 774.1
  L3 w15: v1(1874,931) 1874,825 2128.3,570.7 2128.3,387.7 2167,349 v1(2194,349)
  BOTTOM w15: v1(2194,349) 2194,338 2200.68,331.32 R121.1@2224,331.32
3V3: C28.1 C29.1 C30.1 C31.1 D5.1 L1.2 R133.1 R156.1 U8.21 U8.22 | length 4125
  TOP w15: v1(104,629) 104,657.28 D5.1@105,658.28
  L4 w20: v1(104,629) 115.2,640.2 262,640.2 350.93,551.26 350.93,332.07 385,298 716,298 1057.61,-43.61 1598.66,-43.61 1651.36,-96.31 1802.03,-96.31 1833.22,-127.5 2170.81,-127.5 2216.3,-173 2629,-173 2688.36,-113.64 2688.36,-5.63 2627.73,55 ; v1(2506,55) 2627.73,55 ; v1(2913,536) 2913,340.27 2627.73,55
  BOTTOM w10: U8.22@2495.63,86.19 2495.63,65.37 v1(2506,55) 2515.31,64.31 U8.21@2515.31,86.19
  BOTTOM w15: C28.1@2494.45,28.45 2494.45,43.45 v1(2506,55)
3V3_REF: C22.1 C35.1 C36.2 C46.1 C54.2 C59.1 C81.1 L4.1 L10.1 R37.1 R38.2 R41.2 R43.2 R120.1 R131.2 R132.2 R141.1 R142.2 R156.2 R186.2 S1.4 S1.5 S1.6 U4.5 U4.13 U4.14 U4.27 U4.28 | length 4316.4
  TOP w10: R41.2@2138.24,1950.98 2143.02,1950.98 v1@2161,1933 ; R37.1@2160,2047.68 2176,2063.68 v1(2176,2083)
  TOP w20: S1.6@426.71,105 S1.5@426.71,205 S1.4@426.71,305 453,305 v1(509,361) ; R43.2@1663.51,1892 1664,1891.51 v1(1664,1862) ; v1@1668.11,1990.39 R38.2@1668.11,2021.84
  L3 w20: v1(509,361) 701.27,553.27 835.83,553.27 845.9,543.2 1155.2,543.2 1229,617 v1(1274,617)
  L4 w20: v1(1274,617) 1305.05,648.05 1467.05,648.05 v1(1627,808) 1664,845 v1(1664,1005) 1664,1186.47 1710.4,1232.87 1710.4,1693.66 1710.33,1693.73 1710.33,1716.27 1710.4,1716.34 1710.4,1815.6 v1(1664,1862) 1667,1865 v1(1667,1987) 1667,2055.47 1688.73,2077.2 1689.2,2077.2 1697,2085 1809,2085 1846,2122 2158,2122 2175.2,2104.8 2175.2,2083.8 v1(2176,2083) 2189,2070 2189,1961 v1(2162,1934)
  BOTTOM w10: R186.2@1775.62,516 v1(1824,516) ; 2161.43,528.43 U4.5@2161.43,556.78 ; R141.1@2579,376.32 v1(2619.32,376.32)
  BOTTOM w12: C22.1@2153.38,503 2154,503.62 2154,521 2161.43,528.43
  BOTTOM w16: R132.2@2144,832 2144,835 v1(2163,854) 2179,838 R131.2@2179,832
  BOTTOM w20: R120.1@1603.68,1038 1649,1038 1659,1048 1663,1044 1664,1043 v1(1664,1005) ; v1(1627,808) 1671,764 1744,764 1765,743 ; C22.1@2153.38,503 2153.38,479.38 v1(2153,479) 2173.62,458.38 R142.2@2173.62,453
  other v1: 1848,500 1872,514 2718,594 2718,623 2601.93,628.3 2601.45,657.58 1855,711 1826,712 1827,741 1854,741 1880,742
5VBST: C82.1 C93.1 R78.2 U4.8 | length 1709.4
  TOP w20: v1(840,880) R78.2@950.31,880 R78.2@951.1,880
  L3 w15: v1(840,880) 855,895 992.5,895 1047.5,840 1384,840 1647.21,576.79 1881.21,576.79 v1(2012,446)
  BOTTOM w10: C82.1@2076.62,502 2076.62,522.62 2102.37,548.37 U4.8@2102.37,556.78
  BOTTOM w15: C93.1@2013,384 2012,385 2012,390 v1(2012,446) 2052,446 2076.62,470.62 C82.1@2076.62,502
+3.3VD: C20.2 C41.1 C42.2 C43.2 C50.2 C61.1 C76.1 C86.2 C97.2 R3.2 R14.2 R15.2 R16.2 R68.2 R74.2 R90.2 R91.2 R103.2 R117.2 R124.2 R127.2 R130.2 R133.2 R134.2 R140.2 R155.2 R170.2 R171.2 R172.2 R173.2 R177.1 R194.1 R196.2 R197.2 R200.2 R201.2 R202.2 S2.1 U3.5 U6.7 U6.8 U6.16 U6.26 U6.28 U6.39 U6.47 U6.51 U6.52 U6.69 U6.79 U6.90 U6.101 U6.113 U6.122 U11.1 U11.2 U14.14 | length 17597
  TOP w8: U14.14@1150.24,1260.13 1163.87,1260.13 1179,1245 C97.2@1195.31,1245
  TOP w12: v1(346,1056) 354.7,1047.3 U11.2@381.78,1047.3 ; v1(346,1084.59) 361.41,1084.59 373.11,1072.89 U11.1@381.78,1072.89
  TOP w15: v1(179.5,883) 184.9,888.4 R201.2@184.9,911.21 193.92,911.21 194.38,911.67 208.43,911.67 R200.2@222.7,897.4
  TOP w20: v1(-47,561) -46.31,560.31 R103.2@-18,560.31 ; v1(3.86,1221.14) R74.2@31.96,1221.14 ; R197.2@177.8,996.71 149,967.91 149,896 162,883 v1(179.5,883) ; v1(199,817) 207,809 R90.2@207,790.69 ; v1(216,1572.05) 216.79,1572.84 R68.2@246.04,1572.84 ; R117.2@308.61,475.84 v1(308.61,507) ; C86.2@390.11,1129.1 v1(390.11,1163.89) ; R194.1@544.9,1110.69 571.81,1110.69 v1(584.1,1098.4) ; v1(788,157) 818.36,157 v1(870.18,208.82) 950.36,289 1474,289 1521,336 1521,368.62 R171.2@1496.62,393 R170.2@1496.62,441 v1(1531,441) ; C20.2@986.88,798.85 986.88,827.68 v1(988.2,829) 1001.2,842 1030.31,842 1041.31,831 ; U3.5@1041.31,799.63 1041.31,831 ; R15.2@1114,2118.16 1114,2071.8 v1(1120.4,2065.4) ; v1(1194,1274) 1195.31,1272.69 C97.2@1195.31,1245 ; v1(1236,1345) 1326,1345 1448.72,1222.28 S2.1@1492.9,1222.28 1549.28,1222.28 1566.29,1239.29 v1(1566.29,1243.29) ; R177.1@1246.5,890.03 1187.14,890.03 1143,845.9 1056.21,845.9 1041.31,831 ; v1(1848,1063) 1840.2,1055.2 1840.2,881.51 R3.2@1864.61,857.1 1864.61,847.07 1972.69,739 2111.13,739 2129.71,757.59 2129.71,825.73 2117.13,838.31 R196.2@2098,838.31
  L3 w20: v1(1531,441) 1846,126 2225,126 2309.8,210.8 2309.8,248.58 2547,485.78 v1(2547,576) ; v1(1566.29,1243.29) 1567.12,1243.29 1567.12,1219.03 1585.14,1201.01 1610.62,1201.01 1627.61,1218 1725,1218 1848,1095 v1(1848,1063)
  L3 w32: v1(199,817) 199,795 232,762 703.45,762 786.84,845.39 854.46,845.39 874.07,865 967,865 988.2,843.8 v1(988.2,829)
  L4 w25: v1(216,1572.05) 216,1433.28 v1(3.86,1221.14) -43,1174.28 -43,1011 61,907 155.5,907 v1(179.5,883) 179.5,882.5 v1(135,838) 91,794 33,794 -47,714 v1(-47,561) 254.61,561 v1(308.61,507) 308.61,331.39 382,258 687,258 v1(788,157) ; v1(600,1849.5) 553.8,1803.3 486.6,1803.3 440.5,1849.4 419.6,1849.4 v1(380,1889) 359,1910 359,2179 511.1,2331.1 700.9,2331.1 739.6,2292.4 860.6,2292.4 912.5,2240.5 ; v1(1120.4,2065.4) 1120.4,2094.6 1085.7,2129.3 986.7,2129.3 912.5,2203.5 912.5,2240.5 ; v1(1194,1274) 1236,1316 v1(1236,1345) 1189,1392 1169,1392 1141.87,1419.13 1141.87,1704 1119,1726.87 1119,1864 1146,1891 1222.8,1891 1274,1942.2 1274,2000 1381,2107 1381,2246 1274,2353 998.5,2353 v1(984.6,2339.1) 984.6,2312.6 912.5,2240.5
  L4 w30: v1(584.1,1098.4) 965.6,1098.4 1015,1049 1015,970.24 988.2,943.44 v1(988.2,829)
  BOTTOM w7: 152.35,1397.65 253.34,1397.65 ; 166.23,1240.17 255.57,1240.17 ; 171.36,1429.14 254.24,1429.14 ; U6.7@208.64,1098.43 245.36,1098.43 246.03,1099.1 257.92,1099.1 265.67,1106.85 258.34,1114.18 U6.8@208.64,1114.18 ; 362.18,899.98 362.18,991.42 ; 362.18,1512.18 362.18,1595.98 ; U6.47@488.17,1551.19 488.17,1582.5 499.68,1594.01 ; U6.113@503.92,944.89 503.92,974.56 520.86,991.5 ; U6.51@551.16,1551.19 551.16,1605.41 558.3,1612.55 566.91,1603.94 U6.52@566.91,1551.19 ; 692.89,903.5 692.89,994.61 ; 767,1098.5 814.87,1098.5 U6.90@814.94,1098.43 ; 767.13,1429.14 850.37,1429.14 ; 770.3,1271.66 U6.79@814.94,1271.66
  BOTTOM w8: 850.37,1429.14 864.52,1414.99 893.34,1414.99
  BOTTOM w8.4: 360,1510 362.18,1512.18
  BOTTOM w12: C50.2@146.21,1429.14 171.36,1429.14
  BOTTOM w15: C61.1@146.95,1240.06 147.06,1240.17 166.23,1240.17
  BOTTOM w20: R202.2@45,799.69 45,854 64,873 118,873 135,856 v1(135,838) 156,817 R91.2@156,792.69 ; C50.2@146.21,1429.14 145.95,1429.4 C50.2@145.95,1429.01 145.95,1404.05 152.35,1397.65 ; R140.2@146.55,1199.52 146.55,1239.66 C61.1@146.95,1240.06 ; v1(179.5,883) 222.25,840.25 ; v1(199,817) 222.25,840.25 ; v1(216,1572.05) 216,1670 285.5,1739.5 285.5,1794.5 v1(380,1889) ; 253.34,1397.65 283.85,1397.65 301,1380.5 ; 254.24,1429.14 294.14,1429.14 360,1495 360,1510 ; 255.57,1240.17 289.17,1240.17 301.5,1252.5 v1(390.11,1163.89) ; 265.67,1106.85 323.74,1106.85 v1(346,1084.59) ; 301,1255.5 301,1380.5 ; 362.18,899.98 361.92,899.72 361.92,881.15 ; 362.18,991.42 346,1007.6 v1(346,1056) v1(346,1084.59) ; 362.18,1595.98 362.18,1610.21 483.48,1610.21 499.68,1594.01 C42.2@518.22,1612.55 ; 481.14,1612.55 C42.2@518.22,1612.55 ; 520.86,991.5 541.86,1012.5 675,1012.5 692.89,994.61 714,1015.72 714,1074.5 738,1098.5 767,1098.5 ; v1(600,1849.5) 603.5,1846 R16.2@629.31,1846 ; R124.2@637.72,1612.95 558.7,1612.95 558.3,1612.55 C42.2@518.22,1612.55 ; 692.89,903.5 692.78,903.39 R155.2@692.78,880.84 692.78,880.05 634.85,880.05 560.8,806 426,806 405,827 405,863.5 387.35,881.15 361.92,881.15 ; R173.2@759.88,180.84 775.16,180.84 788,168 v1(788,157) v1@788,155.96 ; 767.13,1429.14 349.64,1429.14 301,1380.5 ; 770.3,1271.66 702.96,1271.66 640.8,1209.5 470.5,1209.5 424.89,1163.89 v1(390.11,1163.89) ; v1(870.18,208.82) 874,205 R172.2@874,181.69 ; 893.34,1414.99 901.99,1414.99 913.55,1426.55 R134.2@913.55,1440.6 ; v1(984.6,2339.1) 988.1,2342.6 R14.2@1023.21,2342.6 ; v1(2547,576) 2571,576 2588.5,558.5 R130.2@2588.5,522 2589.5,521 2715.5,521 2718.5,524 R133.2@2718.5,520 ; 222.25,840.25 223.5,839 304.67,839 346.82,881.15 361.92,881.15 ; v1(346,1084.59) 373.59,1084.59 390.11,1101.11 v1(390.11,1163.89)
AR_1P0_RF1: C19.1 C45.2 C47.2 C98.1 C100.1 L8.2 R46.2 U2.G5 U2.H5 U2.J5 | length 97
  TOP w20: U2.J5@2371.32,1503.49 2373.2,1501.61 U2.H5@2373.2,1477.9 ; v1(2389,1457) 2384.31,1452.31 U2.G5@2371.32,1452.31 2373.2,1454.19 2373.2,1457 U2.H5@2373.2,1477.9 ; v1(2394.83,1485.23) 2380.53,1485.23 U2.H5@2373.2,1477.9
AR_1P0_RF2: C37.1 C57.2 C58.2 C102.1 C103.1 L9.2 R100.2 R137.1 U2.C2 U2.D2 | length 162.3
  TOP w20: U2.C2@2448.09,1349.95 U2.D2@2448.09,1375.54 2480.76,1375.54 2520.35,1335.95 v1(2520.35,1318.1)
  TOP w25: v1(2520.35,1318.1) 2549.1,1318.1 v1(2550.1,1317.1)
AR_1V4_APLL: C13.2 U2.A10 | length 86.4
  TOP w12: 2238.3,1290 2238.3,1293.7 U2.A10@2243.37,1298.77
  TOP w18: C13.2@2234,1232 2238.3,1236.3 2238.3,1290
  TOP w20: C13.2@2226.5,1219.4 2234,1226.9 C13.2@2234,1232
AR_1V4_SYNTH: C14.2 U2.B13 | length 147.9
  TOP w4: 2153.31,1285.31 2153.31,1304.57 ; 2153.52,1304.35 2153.52,1311.28
  TOP w6: 2153.52,1311.28 U2.B13@2166.6,1324.36
  TOP w10: 2141.1,1260 2153.31,1272.2 2153.31,1285.31
  TOP w15: C14.2@2084.45,1220.9 2094.95,1231.4 2112.5,1231.4 2141.1,1260
AR_1V8: C12.2 C17.2 C39.2 C48.2 C51.2 C52.2 C53.2 C90.2 C99.1 C104.1 L6.2 R150.2 U2.B11 U2.B12 U2.D15 U2.F5 U2.K5 U2.R9 | length 1648.5
  TOP w10: U2.R9@2268.96,1657.03 2268.96,1678.96 v1(2279,1689) ; U2.K5@2371.32,1529.08 2400,1557.76 v1(2400,1558)
  TOP w12: v1@2087.46,1375.54 2088,1375.54 U2.D15@2115.42,1375.54 ; 2192.19,1269.8 U2.B12@2192.19,1324.36
  TOP w14: C12.2@2167.2,1228.89 2167.2,1244.81 2192.19,1269.8 ; C90.2@2182,1147.69 2184,1147.69 2194,1157.69 2194,1242.39 2213.8,1262.19 ; 2213.8,1314.1 2213.8,1320.38 U2.B11@2217.78,1324.36
  TOP w15: U2.F5@2371.32,1426.72 2375.28,1426.72 2382,1420 2383.99,1420 2386.46,1417.53 v1(2388,1417.53)
  TOP w18: 2213.8,1262.19 2213.8,1314.1
  TOP w20: v1(2143.17,1217.31) 2155.63,1217.31 C12.2@2167.2,1228.89
  L3 w10: v1@2148,1092.6 2189.24,1051.36 2189.24,980.17 2236.9,932.51 2236.9,911.11 2360.61,787.4 2489.27,787.4 2504.83,771.84 2504.83,696.92 2467.75,659.84 2467.75,523.8 2458.27,514.32 v1(2440.32,514.32)
  BOTTOM w14: v1(2088,1375) 2088,1345.69 C53.2@2091.69,1342 ; R150.2@2404.95,514.32 v1(2440.32,514.32)
  BOTTOM w20: C51.2@2387.91,1389.84 2388,1389.93 v1(2388,1417.53) 2400.53,1417.53 ; v1(2400,1558) 2414.35,1572.35 ; 2414.35,1571.55 2414.35,1572.35 ; C39.2@2420.31,1629 2420.31,1578.31 2414.35,1572.35
  BOTTOM w25: v1@2278.75,1688.75 2294.81,1672.69 2329,1672.69 2343.08,1672.69 2384,1631.77 2384,1631 2386,1629 C39.2@2420.31,1629
  other v1: 2148.05,1093.5 2147.62,1120.27 2147.62,1145.62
